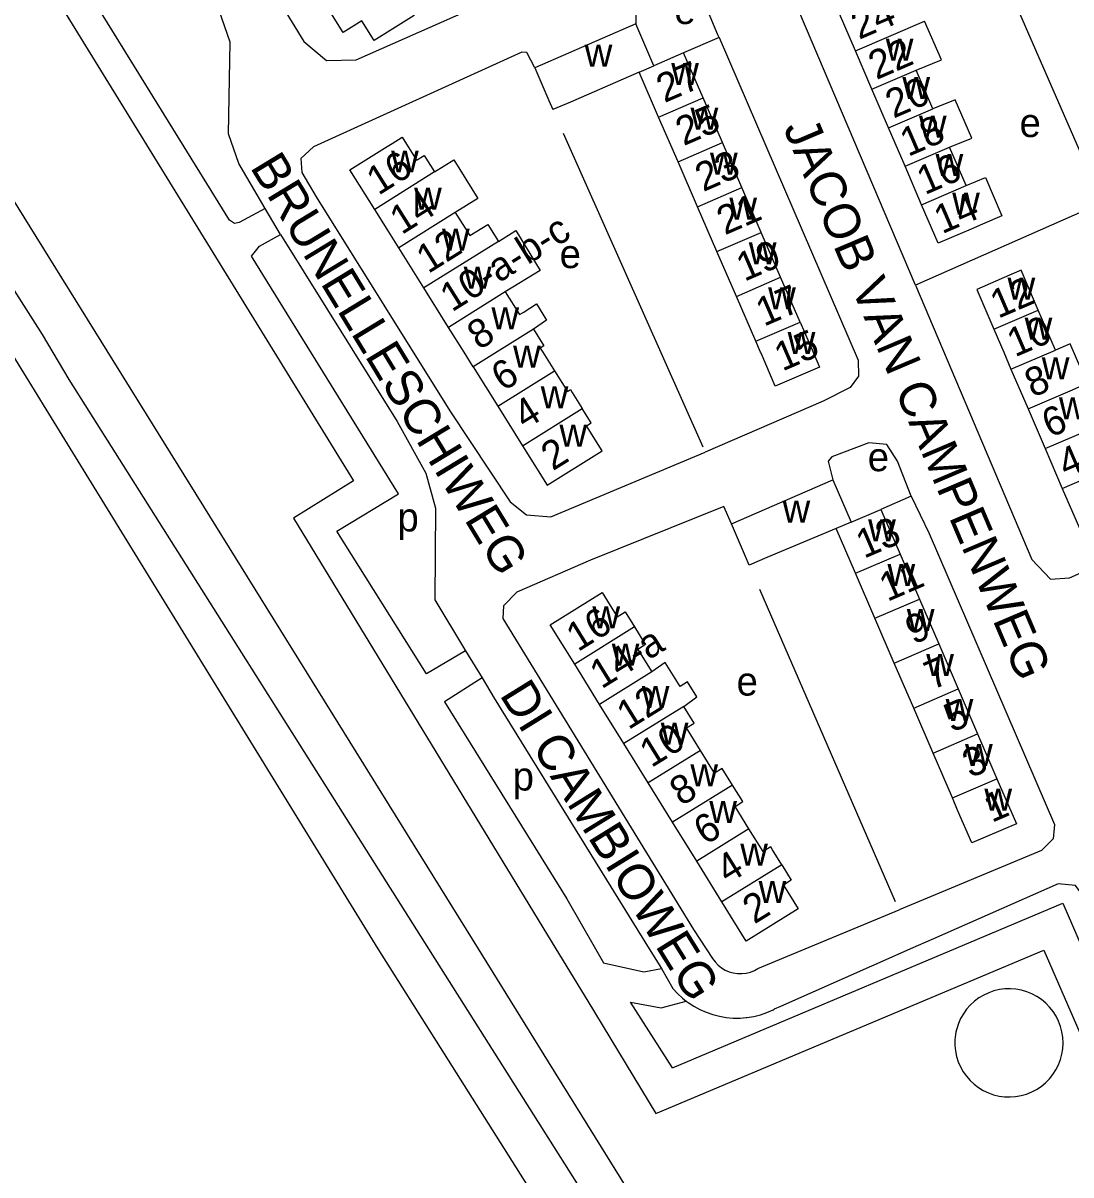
# Model space of a CAD drawing. Extents: x 158848 to 160613, y 385889 to 387762.
# Drawn here: x 159449.2 to 159595.5, y 386135.1 to 386296 of the extents above; entities that cross this region are included whole.
import ezdxf

# ---------------------------------------------------------------- set-up
doc = ezdxf.new("R2010")
doc.units = 0
for name, color, linetype in [('BLT_Basislijn', 7, 'Continuous'), ('BLT_Bebouwing', 7, 'Continuous'), ('BLT_Centroide', 7, 'Continuous'), ('BLT_Huisnummer', 7, 'Continuous'), ('BLT_Huisnummer_ tussenligend', 7, 'Continuous'), ('BLT_Huisnummer_reeks', 7, 'Continuous'), ('BLT_Onderverdeling_panden', 7, 'Continuous'), ('BLT_Straatnaam', 7, 'Continuous')]:
    doc.layers.add(name, color=color, linetype=linetype)

msp = doc.modelspace()

# ---------------------------------------------------------------- linework, layer by layer
at = {"layer": 'BLT_Basislijn'}
for p, q in [((159599.85, 386270.89), (159578.22, 386320.6)), ((159573.77, 386259.36), (159552.48, 386309.54)), ((159546.35, 386293.97), (159541.4, 386291.82)), ((159546.35, 386293.97), (159565.77, 386248.91)), ((159518.79, 386291.91), (159489.7, 386278.72)), ((159519.52, 386291.88), (159518.79, 386291.91)), ((159520.6, 386289.76), (159519.52, 386291.88)), ((159524.56, 386280.59), (159544.1, 386236.79)), ((159489.7, 386278.72), (159487.95, 386277.07)), ((159487.95, 386277.07), (159488.1, 386275.12)), ((159488.1, 386275.12), (159490.1, 386271.71)), ((159490.1, 386271.71), (159508.77, 386241.83)), ((159485.12, 386266.48), (159482.97, 386270.09)), ((159599.85, 386270.89), (159573.77, 386259.36)), ((159565.77, 386248.91), (159565.8, 386246.67)), ((159565.8, 386246.67), (159564.65, 386245.09)), ((159564.65, 386245.09), (159560.9, 386243.18)), ((159560.9, 386243.18), (159544.42, 386236.07)), ((159508.77, 386241.83), (159517.2, 386229.11)), ((159522.85, 386227.04), (159544.42, 386236.07)), ((159495.3, 386232.05), (159486.91, 386226.83)), ((159493, 386225.04), (159501.6, 386230.25)), ((159573.17, 386229.92), (159568.94, 386228.03)), ((159573.17, 386229.92), (159575.66, 386224.7)), ((159517.2, 386229.11), (159519.44, 386227.3)), ((159546.99, 386228.47), (159528.38, 386220.95)), ((159548.07, 386226.06), (159546.99, 386228.47)), ((159519.44, 386227.3), (159522.85, 386227.04)), ((159505.48, 386205.08), (159493, 386225.04)), ((159575.66, 386224.7), (159593.16, 386184.03)), ((159528.38, 386220.95), (159518.11, 386216.52)), ((159571, 386173.26), (159552.04, 386216.86)), ((159518.11, 386216.52), (159516.24, 386214.61)), ((159516.24, 386214.61), (159516.17, 386212.82)), ((159516.17, 386212.82), (159542.77, 386169.37)), ((159510.96, 386208.29), (159505.48, 386205.08)), ((159510.96, 386208.29), (159513.25, 386204.52)), ((159513.25, 386204.52), (159508, 386201.16)), ((159513.25, 386204.52), (159514.95, 386201.71)), ((159593.16, 386184.03), (159593, 386182.03)), ((159593, 386182.03), (159591.35, 386180.41)), ((159591.35, 386180.41), (159571.48, 386172.14)), ((159542.77, 386169.37), (159545.42, 386165.34)), ((159571.72, 386166.07), (159554.9, 386158.61)), ((159538.29, 386163.92), (159539.9, 386161.16)), ((159528, 386159.39), (159537.53, 386143.67)), ((159539.84, 386150.07), (159533.99, 386159.25)), ((159554.9, 386158.61), (159554.04, 386158.23)), ((159522.5, 386150.89), (159551.98, 386103.4))]:
    msp.add_line(p, q, dxfattribs=at)
for points in [[(159473, 386432.36), (159462.11, 386420.94), (159440.16, 386392.21), (159414.81, 386370.75), (159413.46, 386368.41), (159413.43, 386365.42), (159415.73, 386361.26), (159495.3, 386232.05)], [(159356.01, 386401.63), (159357.72, 386400.83), (159362.85, 386393.64), (159414.93, 386310.52), (159451.83, 386252.49), (159455.56, 386246.19), (159505.79, 386166.67), (159542.85, 386107.99), (159548.32, 386099.77)], [(159382.2, 386376.88), (159512.71, 386166.67), (159522.5, 386150.89)], [(159458.38, 386342.3), (159488.36, 386293.44), (159491.54, 386290.75), (159495.68, 386290.84), (159516.34, 386300.01)], [(159482.97, 386270.09), (159479.35, 386268.12), (159478.69, 386267.99), (159477.99, 386268.46), (159440.73, 386328.77), (159440.95, 386329.15), (159452.9, 386336.22)], [(159482.97, 386270.09), (159479.29, 386276.39), (159477.85, 386280.53), (159478.1, 386293.32), (159476.49, 386297.87), (159452.9, 386336.22)], [(159546.35, 386293.97), (159546.18, 386294.37), (159543.24, 386301.41), (159542.61, 386302.11), (159534.7, 386298.8), (159534.73, 386295.87)], [(159422.8, 386289.62), (159436.02, 386268.54), (159498.7, 386166.67), (159546.03, 386091.72)], [(159501.6, 386230.25), (159481.04, 386263.45), (159482.19, 386264.83), (159485.12, 386266.48)], [(159485.12, 386266.48), (159501.39, 386240.33), (159505.41, 386233.13), (159506.73, 386228.21), (159506.65, 386215.41), (159510.96, 386208.29)], [(159573.77, 386259.36), (159590.01, 386221.04), (159592.62, 386218.3), (159595.26, 386218.51), (159618.05, 386228.56)], [(159573.17, 386229.92), (159571.24, 386234.81), (159569.75, 386237.14), (159567.26, 386237.35), (159562.08, 386235.39), (159561.6, 386234.81), (159562.24, 386232.17)], [(159486.91, 386226.83), (159523.57, 386166.67), (159528, 386159.39)], [(159508, 386201.16), (159525.11, 386173.65), (159529.09, 386166.67), (159530.2, 386164.72)], [(159514.95, 386201.71), (159536.6, 386166.67), (159538.29, 386163.92)], [(159609.07, 386139.07), (159611.6, 386140.75), (159600.55, 386166.67), (159598.29, 386172.61), (159596.12, 386175.54), (159593.67, 386175.76), (159576.29, 386168.09)], [(159539.84, 386150.07), (159594.32, 386173.04), (159609.07, 386139.07)], [(159551.78, 386163.92), (159558.36, 386166.67), (159571.48, 386172.14)], [(159576.29, 386168.09), (159573.07, 386166.67), (159571.72, 386166.07)], [(159537.53, 386143.67), (159591.7, 386166.51), (159602.39, 386141.9)], [(159545.42, 386165.34), (159545.78, 386164.85), (159546.2, 386164.41), (159546.67, 386164.03), (159547.19, 386163.72), (159547.75, 386163.47), (159548.33, 386163.31), (159548.93, 386163.22), (159549.54, 386163.21), (159550.14, 386163.28), (159550.73, 386163.42), (159551.29, 386163.65), (159551.78, 386163.92)], [(159530.2, 386164.72), (159535.86, 386163.47), (159538.29, 386163.92)], [(159539.9, 386161.16), (159540.55, 386160.44), (159541.26, 386159.79), (159541.76, 386159.39)], [(159594.38, 386153.49), (159594.34, 386154.32), (159594.22, 386155.09), (159594.02, 386155.84), (159593.75, 386156.57), (159593.4, 386157.26), (159592.99, 386157.92), (159592.5, 386158.53), (159591.96, 386159.09), (159591.36, 386159.59), (159590.72, 386160.02), (159590.03, 386160.39), (159589.32, 386160.68), (159588.57, 386160.9), (159587.8, 386161.04), (159587.03, 386161.1), (159586.25, 386161.08), (159585.48, 386160.98), (159584.72, 386160.81), (159583.99, 386160.55), (159583.29, 386160.22), (159582.62, 386159.83), (159581.99, 386159.36), (159581.42, 386158.83), (159580.91, 386158.25), (159580.46, 386157.62), (159580.07, 386156.94), (159579.76, 386156.23), (159579.49, 386155.35)], [(159533.99, 386159.25), (159538.25, 386158.45), (159541.76, 386159.39)], [(159541.76, 386159.39), (159542.01, 386159.19), (159542.82, 386158.66), (159543.67, 386158.2), (159544.55, 386157.81), (159545.46, 386157.49), (159546.39, 386157.25), (159547.34, 386157.09), (159548.31, 386157.01), (159549.27, 386157), (159550.12, 386157.07)], [(159550.12, 386157.07), (159550.23, 386157.08), (159551.18, 386157.24), (159552.12, 386157.47), (159553.03, 386157.78), (159553.91, 386158.17), (159554.04, 386158.23)], [(159579.42, 386155.04), (159579.36, 386154.73), (159579.27, 386153.96), (159579.27, 386153.18), (159579.35, 386152.41), (159579.51, 386151.65), (159579.74, 386150.91), (159580.05, 386150.19), (159580.43, 386149.51), (159580.88, 386148.88), (159581.39, 386148.29), (159581.96, 386147.76), (159582.58, 386147.29), (159583.24, 386146.89), (159583.94, 386146.56), (159584.68, 386146.3), (159585.43, 386146.12), (159586.2, 386146.01), (159586.98, 386145.99), (159587.75, 386146.05), (159588.52, 386146.18), (159589.27, 386146.39), (159589.99, 386146.68), (159590.68, 386147.04), (159591.32, 386147.47), (159591.92, 386147.97), (159592.47, 386148.52), (159592.95, 386149.12)], [(159579.49, 386155.35), (159579.42, 386155.04)], [(159592.95, 386149.12), (159593.38, 386149.78), (159593.73, 386150.48), (159594.01, 386151.2), (159594.21, 386151.95), (159594.34, 386152.72), (159594.38, 386153.49)]]:
    msp.add_lwpolyline(points, dxfattribs=at)
at = {"layer": 'BLT_Bebouwing'}
for p, q in [((159565.37, 386292.11), (159563.14, 386297.28)), ((159534.73, 386295.87), (159520.6, 386289.76)), ((159537.25, 386290.02), (159534.73, 386295.87)), ((159541.4, 386291.82), (159537.25, 386290.02)), ((159544.11, 386285.55), (159541.4, 386291.82)), ((159567.68, 386286.74), (159565.37, 386292.11)), ((159535.2, 386289.13), (159525.58, 386284.96)), ((159537.91, 386282.87), (159535.2, 386289.13)), ((159576.19, 386284.03), (159573.88, 386289.41)), ((159570, 386281.36), (159567.68, 386286.74)), ((159525.58, 386284.96), (159523.13, 386283.91)), ((159546.82, 386279.29), (159544.11, 386285.55)), ((159540.63, 386276.6), (159537.91, 386282.87)), ((159572.32, 386275.99), (159570, 386281.36)), ((159549.53, 386273.02), (159546.82, 386279.29)), ((159580.83, 386273.29), (159578.51, 386278.66)), ((159543.34, 386270.34), (159540.63, 386276.6)), ((159574.63, 386270.62), (159572.32, 386275.99)), ((159552.23, 386266.75), (159549.53, 386273.02)), ((159546.05, 386264.07), (159543.34, 386270.34)), ((159554.94, 386260.48), (159552.23, 386266.75)), ((159505.13, 386259.01), (159501.63, 386264.6)), ((159548.77, 386257.81), (159546.05, 386264.07)), ((159557.65, 386254.22), (159554.94, 386260.48)), ((159508.58, 386253.48), (159505.13, 386259.01)), ((159551.48, 386251.54), (159548.77, 386257.81)), ((159593.32, 386250.31), (159590.92, 386255.9)), ((159512.02, 386247.99), (159515.46, 386242.47)), ((159587.1, 386247.67), (159589.49, 386242.11)), ((159515.46, 386242.47), (159518.91, 386236.96)), ((159589.49, 386242.11), (159591.87, 386236.55)), ((159591.87, 386236.55), (159594.26, 386230.99)), ((159548.07, 386226.06), (159562.24, 386232.17)), ((159562.24, 386232.17), (159564.78, 386226.28)), ((159564.78, 386226.28), (159568.94, 386228.03)), ((159568.94, 386228.03), (159571.62, 386221.81)), ((159562.7, 386225.41), (159553.02, 386221.34)), ((159565.4, 386219.13), (159562.7, 386225.41)), ((159571.62, 386221.81), (159574.32, 386215.54)), ((159553.02, 386221.34), (159550.56, 386220.28)), ((159568.11, 386212.86), (159565.4, 386219.13)), ((159574.32, 386215.54), (159577.03, 386209.26)), ((159570.81, 386206.58), (159568.11, 386212.86)), ((159577.03, 386209.26), (159579.73, 386202.98)), ((159529.66, 386200.83), (159526.19, 386206.45)), ((159573.52, 386200.3), (159570.81, 386206.58)), ((159579.73, 386202.98), (159582.44, 386196.71)), ((159533.05, 386195.35), (159529.66, 386200.83)), ((159576.22, 386194.03), (159573.52, 386200.3)), ((159582.44, 386196.71), (159585.14, 386190.43)), ((159536.45, 386189.86), (159533.05, 386195.35)), ((159578.93, 386187.76), (159576.22, 386194.03)), ((159539.84, 386184.38), (159536.45, 386189.86)), ((159543.23, 386178.91), (159539.84, 386184.38)), ((159546.75, 386173.22), (159543.23, 386178.91))]:
    msp.add_line(p, q, dxfattribs=at)
for points in [[(159498.97, 386305.52), (159500, 386303.86), (159500.38, 386303.25), (159500, 386303.02), (159499.31, 386302.59), (159500, 386301.48), (159501.35, 386299.31), (159502.07, 386299.77), (159503.77, 386297.04), (159498.18, 386293.57), (159496.48, 386296.29), (159493.88, 386294.68), (159490.44, 386300.23)], [(159573.88, 386289.41), (159577.38, 386290.85), (159575.03, 386296.28)], [(159520.6, 386289.76), (159522.58, 386285.17), (159523.13, 386283.91)], [(159578.51, 386278.66), (159581.62, 386279.93), (159579.32, 386285.27), (159576.19, 386284.03)], [(159498.27, 386269.97), (159494.8, 386275.51), (159500, 386278.76), (159500.68, 386279.19), (159502.08, 386280.07), (159504.1, 386276.84), (159505.17, 386277.51), (159506.62, 386275.2)], [(159506.62, 386275.2), (159509.29, 386276.87), (159512.65, 386271.49), (159509.52, 386269.53)], [(159580.83, 386273.29), (159583.53, 386274.42), (159585.84, 386269.08), (159583.14, 386267.91), (159581.54, 386267.22), (159576.95, 386265.24), (159574.63, 386270.62)], [(159501.63, 386264.6), (159500, 386267.21), (159498.27, 386269.97)], [(159509.52, 386269.53), (159511.54, 386266.3), (159514.04, 386267.86), (159515.53, 386265.48)], [(159515.53, 386265.48), (159517.99, 386267.03), (159521.38, 386261.45), (159516.49, 386258.43)], [(159590.92, 386255.9), (159588.53, 386261.46), (159586.91, 386260.76), (159582.32, 386258.79), (159584.71, 386253.23)], [(159516.49, 386258.43), (159518.46, 386255.27), (159518.97, 386255.58), (159520.85, 386256.76), (159522.26, 386254.49), (159520.43, 386253.25)], [(159557.65, 386254.22), (159559.47, 386250), (159560.36, 386247.94), (159554.19, 386245.28), (159552.21, 386249.87), (159552.15, 386250), (159551.48, 386251.54)], [(159512.02, 386247.99), (159510.76, 386250), (159508.58, 386253.48)], [(159520.43, 386253.25), (159521.89, 386250.91), (159521.37, 386250.58), (159521.73, 386250), (159523.35, 386247.4)], [(159584.71, 386253.23), (159586.09, 386250), (159587.1, 386247.67)], [(159595.7, 386244.78), (159597.73, 386245.67), (159595.36, 386251.18), (159593.32, 386250.31)], [(159523.35, 386247.4), (159525.16, 386244.51), (159525.6, 386244.79), (159525.85, 386244.38), (159527.24, 386242.16)], [(159527.84, 386239.73), (159528.5, 386240.14), (159527.24, 386242.16)], [(159518.91, 386236.96), (159522.36, 386231.44), (159530.02, 386236.23), (159527.84, 386239.73)], [(159594.26, 386230.99), (159596.65, 386225.43), (159602.88, 386228.11), (159600.9, 386232.7), (159600.49, 386233.67)], [(159550.56, 386220.28), (159550.05, 386221.47), (159548.07, 386226.06)], [(159526.19, 386206.45), (159522.78, 386211.95), (159530.03, 386216.44), (159532.12, 386213.07), (159533.23, 386213.76), (159534.54, 386211.64)], [(159534.54, 386211.64), (159535.86, 386209.51), (159536.07, 386209.18), (159535, 386208.51), (159536.96, 386205.35)], [(159541.42, 386200.53), (159543.25, 386201.88), (159541.95, 386203.97), (159540.89, 386203.31), (159538.81, 386206.67), (159536.96, 386205.35)], [(159543.74, 386194.38), (159541.79, 386197.54), (159542.86, 386198.21), (159541.42, 386200.53)], [(159548.21, 386189.56), (159546.77, 386191.88), (159545.7, 386191.22), (159543.74, 386194.38)], [(159550.52, 386183.42), (159548.57, 386186.58), (159549.64, 386187.25), (159548.21, 386189.56)], [(159585.14, 386190.43), (159587.85, 386184.16), (159581.63, 386181.48), (159579.65, 386186.07), (159578.93, 386187.76)], [(159555.12, 386178.39), (159553.8, 386180.52), (159553.55, 386180.93), (159552.48, 386180.26), (159550.52, 386183.42)], [(159555.12, 386178.39), (159556.43, 386176.27), (159555.34, 386175.59), (159557.4, 386172.27), (159550.12, 386167.77), (159546.75, 386173.22)]]:
    msp.add_lwpolyline(points, dxfattribs=at)
at = {"layer": 'BLT_Onderverdeling_panden'}
for p, q in [((159565.37, 386292.11), (159575.03, 386296.28)), ((159535.2, 386289.13), (159537.25, 386290.02)), ((159567.68, 386286.74), (159573.88, 386289.41)), ((159537.91, 386282.87), (159544.11, 386285.55)), ((159570, 386281.36), (159576.19, 386284.03)), ((159540.63, 386276.6), (159546.82, 386279.29)), ((159572.32, 386275.99), (159578.51, 386278.66)), ((159506.62, 386275.2), (159498.27, 386269.97)), ((159543.34, 386270.34), (159549.53, 386273.02)), ((159574.63, 386270.62), (159580.83, 386273.29)), ((159509.52, 386269.53), (159501.63, 386264.6)), ((159546.05, 386264.07), (159552.23, 386266.75)), ((159515.53, 386265.48), (159505.13, 386259.01)), ((159548.77, 386257.81), (159554.94, 386260.48)), ((159516.49, 386258.43), (159508.58, 386253.48)), ((159584.71, 386253.23), (159590.92, 386255.9)), ((159551.48, 386251.54), (159557.65, 386254.22)), ((159520.43, 386253.25), (159512.02, 386247.99)), ((159587.1, 386247.67), (159593.32, 386250.31)), ((159515.46, 386242.47), (159523.35, 386247.4)), ((159589.49, 386242.11), (159595.7, 386244.78)), ((159518.91, 386236.96), (159527.24, 386242.16)), ((159591.87, 386236.55), (159598.09, 386239.23)), ((159594.26, 386230.99), (159600.49, 386233.67)), ((159564.78, 386226.28), (159562.7, 386225.41)), ((159565.4, 386219.13), (159571.62, 386221.81)), ((159568.11, 386212.86), (159574.32, 386215.54)), ((159534.54, 386211.64), (159526.19, 386206.45)), ((159570.81, 386206.58), (159577.03, 386209.26)), ((159536.96, 386205.35), (159529.66, 386200.83)), ((159573.52, 386200.3), (159579.73, 386202.98)), ((159541.42, 386200.53), (159533.05, 386195.35)), ((159576.22, 386194.03), (159582.44, 386196.71)), ((159543.74, 386194.38), (159536.45, 386189.86)), ((159548.21, 386189.56), (159539.84, 386184.38)), ((159578.93, 386187.76), (159585.14, 386190.43)), ((159550.52, 386183.42), (159543.23, 386178.91)), ((159555.12, 386178.39), (159546.75, 386173.22))]:
    msp.add_line(p, q, dxfattribs=at)

# ---------------------------------------------------------------- texts
at = {"layer": 'BLT_Centroide'}
for s, p in [('e', (159540.1, 386295.86)), ('w', (159569.62, 386290.75)), ('w', (159527.58, 386289.88)), ('w', (159539.66, 386287.34)), ('w', (159571.94, 386285.38)), ('w', (159542.36, 386281.08)), ('w', (159574.25, 386280)), ('e', (159588.3, 386280.07)), ('w', (159500.55, 386275.12)), ('w', (159545.08, 386274.81)), ('w', (159576.57, 386274.62)), ('w', (159503.77, 386269.94)), ('w', (159547.78, 386268.53)), ('w', (159578.89, 386269.25)), ('w', (159507.66, 386264.22)), ('e', (159524.08, 386261.76)), ('w', (159550.5, 386262.28)), ('w', (159510.7, 386258.88)), ('w', (159586.62, 386257.34)), ('w', (159553.2, 386256)), ('w', (159514.56, 386253.22)), ('w', (159589.01, 386251.78)), ('w', (159555.92, 386249.75)), ('w', (159517.58, 386247.88)), ('w', (159591.4, 386246.22)), ('w', (159521.44, 386242.19)), ('w', (159593.79, 386240.66)), ('w', (159524.06, 386236.81)), ('e', (159567.1, 386233.39)), ('p', (159501.44, 386224.98)), ('w', (159555.21, 386226.22)), ('w', (159567.16, 386223.58)), ('w', (159569.86, 386217.34)), ('w', (159528.66, 386211.44)), ('w', (159572.56, 386211.06)), ('w', (159531.36, 386206.25)), ('w', (159575.27, 386204.78)), ('e', (159548.79, 386202.05)), ('w', (159535.55, 386200.34)), ('w', (159577.98, 386198.5)), ('w', (159538.2, 386195.19)), ('w', (159580.69, 386192.22)), ('w', (159542.34, 386189.38)), ('p', (159517.52, 386188.79)), ('w', (159583.39, 386185.97)), ('w', (159544.98, 386184.25)), ('w', (159549.3, 386178.31)), ('w', (159551.86, 386173.09))]:
    msp.add_text(s, height=4, dxfattribs=at).set_placement(p)
at = {"layer": 'BLT_Huisnummer'}
for s, rotation, p in [('22', 23.325, (159568.31, 386288.02)), ('27', 23.3643, (159538.71, 386284.8)), ('18', 23.325, (159572.73, 386277.28)), ('16', 32.0224, (159498.77, 386271.84)), ('23', 23.3643, (159544.12, 386272.37)), ('14', 23.325, (159577.47, 386266.48)), ('19', 23.3643, (159549.87, 386259.84)), ('12', 23.2608, (159585.31, 386254.67)), ('15', 23.3643, (159555.18, 386247.3)), ('6', 32.0224, (159516.18, 386244.46)), ('6', 23.2608, (159592.53, 386238.02)), ('2', 32.0224, (159523.13, 386233.37)), ('13', 23.3186, (159566.58, 386221.15)), ('16', 31.7435, (159526.63, 386208.1)), ('9', 23.3186, (159573.48, 386209.14)), ('5', 23.3186, (159578.85, 386196.86)), ('10', 31.7435, (159536.88, 386191.9)), ('1', 23.3186, (159584.41, 386184.25)), ('6', 31.7435, (159544.43, 386181.08)), ('2', 31.7435, (159551.26, 386170.06))]:
    msp.add_text(s, height=4, rotation=rotation, dxfattribs=at).set_placement(p)
at = {"layer": 'BLT_Huisnummer_ tussenligend'}
for s, rotation, p in [('24', 23.325, (159565.89, 386293.63)), ('20', 23.325, (159570.69, 386282.63)), ('25', 23.3643, (159541.39, 386278.79)), ('16', 23.325, (159575.07, 386271.94)), ('14', 32.0224, (159502.02, 386266.35)), ('21', 23.3643, (159547.14, 386266.33)), ('12', 32.0224, (159505.72, 386260.91)), ('17', 23.3643, (159552.6, 386253.56)), ('8', 32.0224, (159512.82, 386250.24)), ('10', 23.2608, (159587.66, 386249.28)), ('8', 23.2608, (159590.12, 386243.64)), ('4', 32.0224, (159519.27, 386239.14)), ('4', 23.2608, (159594.77, 386232.44)), ('11', 23.3186, (159569.83, 386215.12)), ('7', 23.3186, (159576.11, 386202.8)), ('12', 31.7435, (159533.68, 386197.2)), ('3', 23.3186, (159581.43, 386190.49)), ('8', 31.7435, (159541.07, 386186.54)), ('4', 31.7435, (159547.56, 386175.67))]:
    msp.add_text(s, height=4, rotation=rotation, dxfattribs=at).set_placement(p)
at = {"layer": 'BLT_Huisnummer_reeks'}
for s, rotation, p in [('10-a-b-c', 32.0224, (159509.04, 386255.55)), ('14-a', 31.7435, (159529.93, 386202.9))]:
    msp.add_text(s, height=4, rotation=rotation, dxfattribs=at).set_placement(p)
at = {"layer": 'BLT_Straatnaam'}
for s, rotation, p in [('JACOB VAN CAMPENWEG', 293.0448, (159555.26, 386281.36)), ('BRUNELLESCHIWEG', 301.2995, (159480.78, 386275.87)), ('DI CAMBIOWEG', 301.7977, (159515.62, 386202.17))]:
    msp.add_text(s, height=5, rotation=rotation, dxfattribs=at).set_placement(p)

doc.saveas('drawing.dxf')
